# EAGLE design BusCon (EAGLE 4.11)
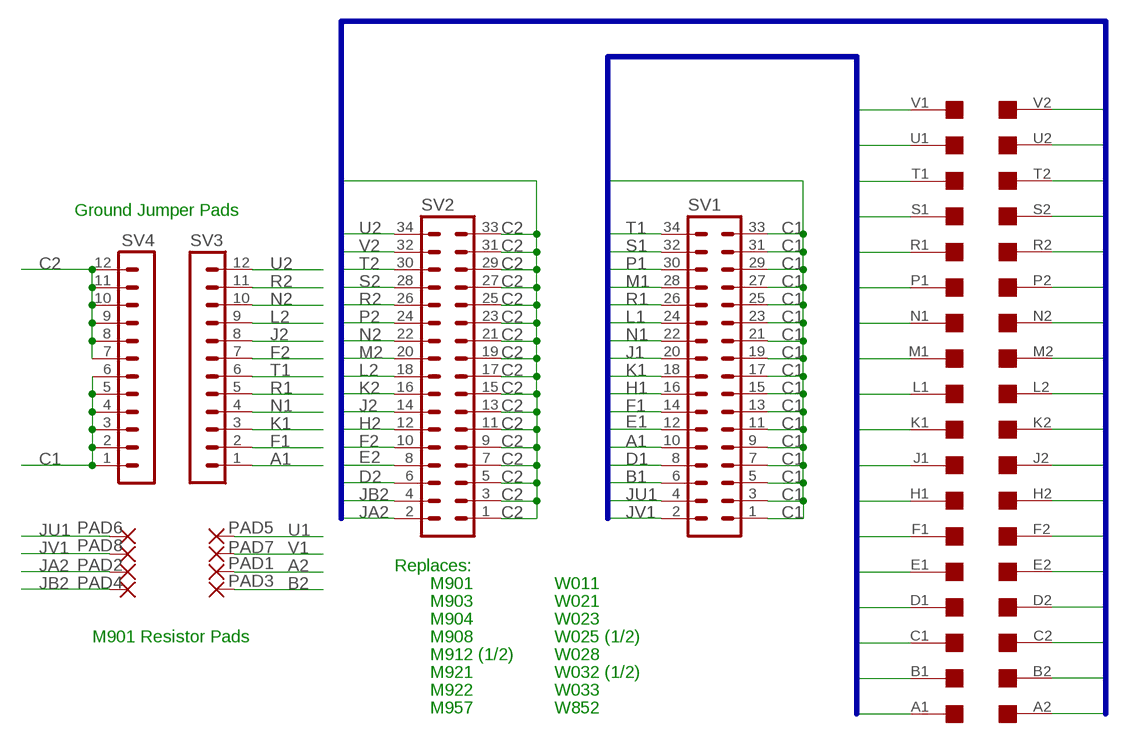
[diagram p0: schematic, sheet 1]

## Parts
PAD1  1,6/0,8  [1,6/0,8]
PAD2  1,6/0,8  [1,6/0,8]
PAD3  1,6/0,8  [1,6/0,8]
PAD4  1,6/0,8  [1,6/0,8]
PAD5  1,6/0,8  [1,6/0,8]
PAD6  1,6/0,8  [1,6/0,8]
PAD7  1,6/0,8  [1,6/0,8]
PAD8  1,6/0,8  [1,6/0,8]
SV1  MA17-2  [MA17-2]
SV2  MA17-2  [MA17-2]
SV3  MA12-1  [MA12-1]
SV4  MA12-1  [MA12-1]
U$4  EDGE-2  [EDGE-CON2]

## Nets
A1: SV1.10 SV3.1 U$4.A1
A2: PAD1.1(P) U$4.A2
B1: SV1.6 U$4.B1
B2: PAD3.1(P) U$4.B2
C1: SV1.1 SV1.3 SV1.5 SV1.7 SV1.9 SV1.11 SV1.13 SV1.15 SV1.17 SV1.19 SV1.21 SV1.23 SV1.25 SV1.27 SV1.29 SV1.31 SV1.33 SV4.1 SV4.2 SV4.3 SV4.4 SV4.5 SV4.6 U$4.C1
C2: SV2.1 SV2.3 SV2.5 SV2.7 SV2.9 SV2.11 SV2.13 SV2.15 SV2.17 SV2.19 SV2.21 SV2.23 SV2.25 SV2.27 SV2.29 SV2.31 SV2.33 SV4.7 SV4.8 SV4.9 SV4.10 SV4.11 SV4.12 U$4.C2
D1: SV1.8 U$4.D1
D2: SV2.6 U$4.D2
E1: SV1.12 U$4.E1
E2: SV2.8 U$4.E2
F1: SV1.14 SV3.2 U$4.F1
F2: SV2.10 SV3.7 U$4.F2
H1: SV1.16 U$4.H1
H2: SV2.12 U$4.H2
J1: SV1.20 U$4.J1
J2: SV2.14 SV3.8 U$4.J2
JA2: PAD2.1(P) SV2.2
JB2: PAD4.1(P) SV2.4
JU1: PAD6.1(P) SV1.4
JV1: PAD8.1(P) SV1.2
K1: SV1.18 SV3.3 U$4.K1
K2: SV2.16 U$4.K2
L1: SV1.24 U$4.L1
L2: SV2.18 SV3.9 U$4.L2
M1: SV1.28 U$4.M1
M2: SV2.20 U$4.M2
N1: SV1.22 SV3.4 U$4.N1
N2: SV2.22 SV3.10 U$4.N2
P1: SV1.30 U$4.P1
P2: SV2.24 U$4.P2
R1: SV1.26 SV3.5 U$4.R1
R2: SV2.26 SV3.11 U$4.R2
S1: SV1.32 U$4.S1
S2: SV2.28 U$4.S2
T1: SV1.34 SV3.6 U$4.T1
T2: SV2.30 U$4.T2
U1: PAD5.1(P) U$4.U1
U2: SV2.34 SV3.12 U$4.U2
V1: PAD7.1(P) U$4.V1
V2: SV2.32 U$4.V2

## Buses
A1,B1,C1,D1,E1,F1,H1,J1,K1,L1,M1,N1,P1,R1,S1,T1,U1,V1
A2,B2,C2,D2,E2,F2,H2,J2,K2,L2,M2,N2,P2,R2,S2,T2,U2,V2

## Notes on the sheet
- Ground Jumper Pads
- Replaces:
- M901 | W011
- M903 | W021
- M904 | W023
- M901 Resistor Pads | M908 | W025 (1/2)
- M912 (1/2) | W028
- M921 | W032 (1/2)
- M922 | W033
- M957 | W852

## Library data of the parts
PAD1-PAD8 = wirepad:1,6/0,8: THROUGH-HOLE PAD
SV1 SV2 = con-lstb:MA17-2: PIN HEADER
SV3 SV4 = con-lstb:MA12-1: PIN HEADER
U$4 = dec-con:EDGE-2: Double-Sided DEC edge connector.

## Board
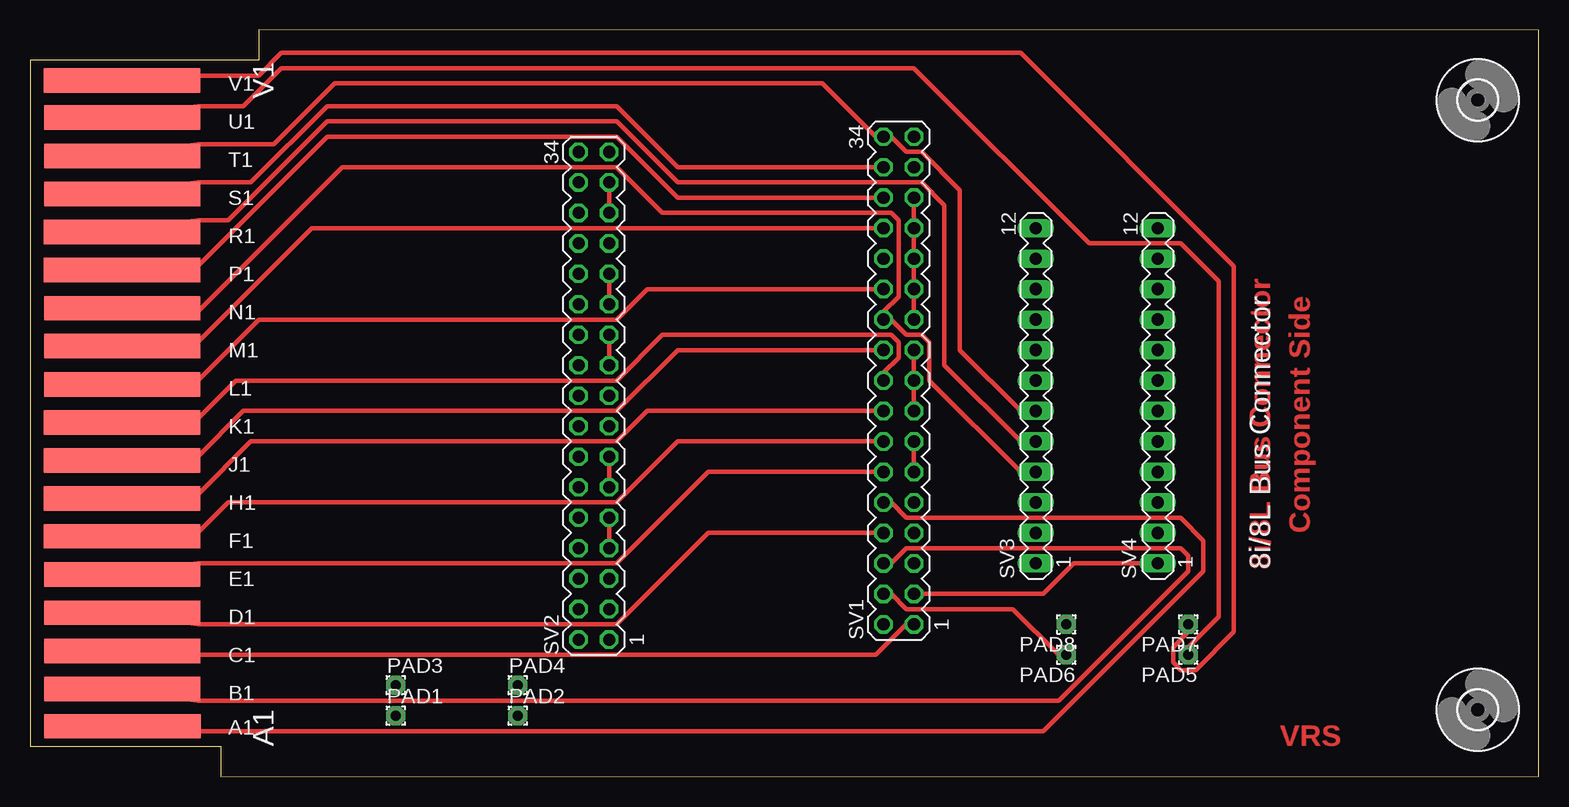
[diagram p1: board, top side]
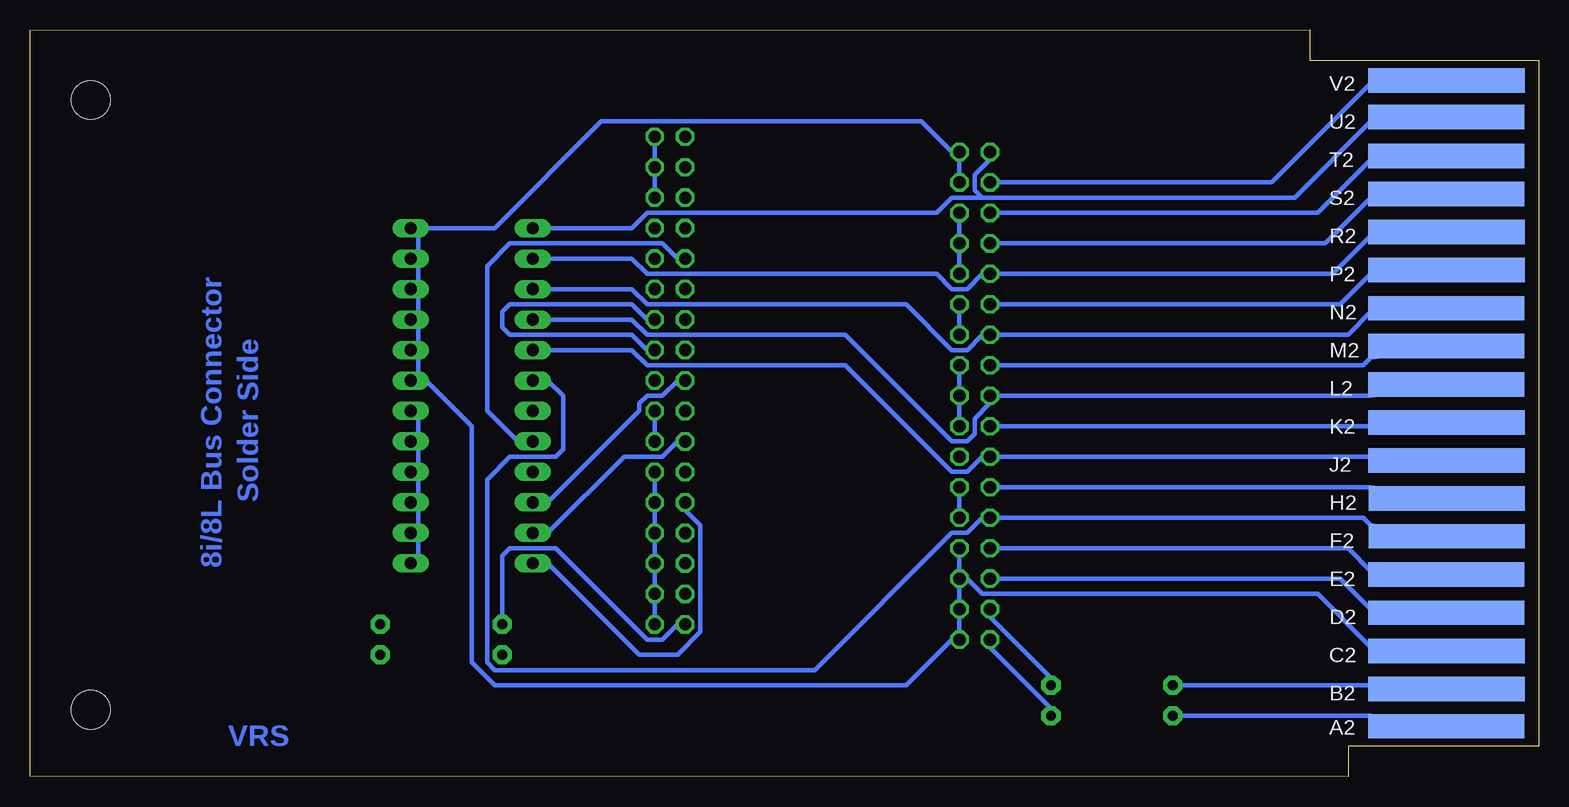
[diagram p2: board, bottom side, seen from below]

Size 125.72 x 62.23 mm. Coordinates in mm from the lower left corner, seen from the top.
Outline: 15.88,0 125.72,0.04 125.72,62.19 19.05,62.23
Copper layers (1*16): Top 0.035mm / dielectric 1.5mm / Bottom 0.035mm
Design rules "olimex10mil": minimum track width 15mil, minimum drill 24mil, track to track 15mil, track to pad 10mil, pad to pad 10mil, via to via 10mil, smd to smd 10mil, copper to edge 25mil, drill to drill 10mil, minimum pad ring 10mil, minimum via ring 8mil, stop-mask expansion 0mil, vias tented up to drill 0mil, thermal gap 10mil

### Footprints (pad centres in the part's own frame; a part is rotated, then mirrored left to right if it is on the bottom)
1,6/0,8 = drill 0.813 pad 1.6 octagon: 1 0,0
MA17-2 = drill 1.016 octagon: 1 -20.32,-1.27; 2 -20.32,1.27; 3 -17.78,-1.27; 4 -17.78,1.27; 5 -15.24,-1.27; 6 -15.24,1.27; 7 -12.7,-1.27; 8 -12.7,1.27; 9 -10.16,-1.27; 10 -10.16,1.27; 11 -7.62,-1.27; 12 -7.62,1.27; 13 -5.08,-1.27; 14 -5.08,1.27; 15 -2.54,-1.27; 16 -2.54,1.27; 17 0,-1.27; 18 0,1.27; 19 2.54,-1.27; 20 2.54,1.27; 21 5.08,-1.27; 22 5.08,1.27; 23 7.62,-1.27; 24 7.62,1.27; 25 10.16,-1.27; 26 10.16,1.27; 27 12.7,-1.27; 28 12.7,1.27; 29 15.24,-1.27; 30 15.24,1.27; 31 17.78,-1.27; 32 17.78,1.27; 33 20.32,-1.27; 34 20.32,1.27
MA12-1 = drill 1.016 long: 1 -13.97,0; 2 -11.43,0; 3 -8.89,0; 4 -6.35,0; 5 -3.81,0; 6 -1.27,0; 7 1.27,0; 8 3.81,0; 9 6.35,0; 10 8.89,0; 11 11.43,0; 12 13.97,0
3,2 = hole 3.2: 0,0
EDGE-CON2 = smd 13.017 x 2.032: A1 7.709,4.207; B1 7.684,7.312; C1 7.684,10.474; D1 7.684,13.665; E1 7.693,16.84; F1 7.668,20.041; H1 7.668,23.19; J1 7.668,26.34; K1 7.668,29.515; L1 7.693,32.69; M1 7.693,35.89; N1 7.693,39.04; P1 7.668,42.24; R1 7.668,45.39; S1 7.693,48.565; T1 7.693,51.74; U1 7.693,54.94; V1 7.668,58.026 | smd 13.017 x 2.032 bottom: A2 7.69,4.207; B2 7.668,7.328; C2 7.668,10.49; D2 7.693,13.665; E2 7.693,16.84; F2 7.642,20.041; H2 7.642,23.19; J2 7.668,26.34; K2 7.668,29.515; L2 7.693,32.69; M2 7.693,35.89; N2 7.693,39.04; P2 7.668,42.24; R2 7.668,45.39; S2 7.693,48.565; T2 7.693,51.74; U2 7.693,54.966; V2 7.668,58.026

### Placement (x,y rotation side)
PAD1  30.48,5.08 0 top
PAD2  40.64,5.08 0 top
PAD3  30.48,7.62 0 top
PAD4  40.64,7.62 0 top
PAD5  96.52,10.16 180 top
PAD6  86.36,10.16 180 top
PAD7  96.52,12.7 180 top
PAD8  86.36,12.7 180 top
SV1  72.39,33.02 90 top
SV2  46.99,31.75 90 top
SV3  83.82,31.75 90 top
SV4  93.98,31.75 90 top
U$2  [3,2]  120.65,5.59 0 top
U$3  [3,2]  120.65,56.39 0 top
U$4  0,0 0 top

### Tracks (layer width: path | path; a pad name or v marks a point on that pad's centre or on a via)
A1
  Top 0.381: SV1.10 71.76,22.86 73.03,21.59 95.89,21.59 97.79,19.68 97.79,17.14 84.46,3.81 13.97,3.81 U$4.A1
  Bottom 0.381: SV1.10 71.12,22.23 69.85,20.95 69.85,12.06 71.76,10.16 74.93,10.16 82.55,17.78 SV3.1
A2
  Bottom 0.381: PAD1.1 29.85,5.08 13.97,5.08 U$4.A2
B1
  Top 0.381: SV1.6 71.76,17.78 73.03,19.05 95.89,19.05 96.52,18.41 96.52,17.14 85.73,6.35 13.97,6.35 U$4.B1
B2
  Bottom 0.381: PAD3.1 29.85,7.62 13.97,7.62 U$4.B2
C1
  Top 0.381: SV1.21 73.66,38.73 73.66,40.01 SV1.23 73.66,41.27 73.66,42.55 SV1.25 73.66,43.81 73.66,45.09 SV1.27 73.66,46.35 73.66,47.62 SV1.29 | SV1.15 73.66,31.11 73.66,32.38 SV1.17 73.66,33.66 73.66,34.92 SV1.19 | SV1.13 73.66,27.3 73.66,26.04 SV1.11 | SV4.1 92.71,17.78 87,17.78 84.46,15.24 74.3,15.24 SV1.3 | U$4.C1 13.97,10.16 70.49,10.16 73.03,12.7 SV1.1
  Bottom 0.381: SV1.29 73.66,48.9 73.66,50.16 SV1.31 73.66,51.44 73.66,52.7 SV1.33 | SV4.1 93.35,18.41 93.35,19.68 SV4.2 93.35,20.95 93.35,22.23 SV4.3 93.35,23.5 93.35,24.77 SV4.4 93.35,26.04 93.35,27.3 SV4.5 93.35,28.57 93.35,29.84 SV4.6 | SV1.13 73.66,28.57 73.66,29.84 SV1.15 | SV1.1 73.66,13.34 73.66,14.61 SV1.3 73.66,15.88 73.66,17.14 SV1.5 73.66,18.41 73.66,19.68 SV1.7 73.66,20.95 73.66,22.23 SV1.9 73.66,23.5 73.66,24.77 SV1.11 | SV1.21 74.3,38.1 75.57,39.37 85.73,39.37 86.36,38.73 86.36,37.47 85.73,36.83 75.57,36.83 74.3,35.56 SV1.19
C2
  Top 0.381: SV2.21 48.26,36.2 48.26,34.92 SV2.19 | SV2.31 48.26,48.9 48.26,47.62 SV2.29 | SV2.23 48.26,40.01 48.26,41.27 SV2.25 | SV2.13 48.26,26.04 48.26,24.77 SV2.11 | SV2.9 48.26,20.95 48.26,19.68 SV2.7
  Bottom 0.381: SV2.21 48.26,37.47 48.26,38.73 SV2.23 | SV2.15 48.26,29.84 48.26,31.11 SV2.17 48.26,32.38 48.26,33.66 SV2.19 | SV2.31 48.26,50.16 48.26,51.44 SV2.33 48.9,52.07 51.44,54.61 78.11,54.61 87,45.72 92.71,45.72 SV4.12 93.35,45.09 93.35,43.81 SV4.11 93.35,42.55 93.35,41.27 SV4.10 93.35,40.01 93.35,38.73 SV4.9 93.35,37.47 93.35,36.2 SV4.8 93.35,34.92 93.35,33.66 SV4.7 92.71,33.02 88.9,29.21 88.9,9.53 87,7.62 52.71,7.62 48.9,11.43 SV2.1 48.26,12.06 48.26,13.34 SV2.3 48.26,14.61 48.26,15.88 SV2.5 | SV2.25 48.26,42.55 48.26,43.81 SV2.27 48.26,45.09 48.26,46.35 SV2.29 | SV2.9 48.26,22.23 48.26,23.5 SV2.11 | SV2.7 48.26,18.41 48.26,17.14 SV2.5 | SV2.5 47.63,16.51 46.36,15.24 18.42,15.24 13.97,10.79 U$4.C2
D1
  Top 0.381: SV1.8 70.49,20.32 56.52,20.32 48.9,12.7 13.97,12.7 U$4.D1
D2
  Bottom 0.381: SV2.6 45.09,16.51 16.51,16.51 13.97,13.97 U$4.D2
E1
  Top 0.381: SV1.12 70.49,25.4 56.52,25.4 48.9,17.78 13.97,17.78 U$4.E1
E2
  Bottom 0.381: SV2.8 45.09,19.05 15.88,19.05 13.97,17.14 U$4.E2
F1
  Top 0.381: SV1.14 70.49,27.94 53.98,27.94 48.9,22.86 16.51,22.86 13.97,20.32 U$4.F1
  Bottom 0.381: SV1.14 71.76,27.94 73.03,26.67 76.2,26.67 82.55,20.32 SV3.2
F2
  Bottom 0.381: U$4.F2 13.97,20.95 14.61,21.59 45.09,21.59 SV2.10 46.36,21.59 47.63,20.32 48.9,20.32 60.33,8.89 87,8.89 87.63,9.53 87.63,24.77 85.73,26.67 81.92,26.67 81.28,27.3 81.28,31.75 82.55,33.02 SV3.7
H1
  Top 0.381: SV1.16 70.49,30.48 51.44,30.48 48.9,27.94 18.42,27.94 13.97,23.5 U$4.H1
H2
  Bottom 0.381: SV2.12 45.09,24.13 13.97,24.13 U$4.H2
J1
  Top 0.381: SV1.20 70.49,35.56 53.98,35.56 48.9,30.48 17.78,30.48 13.97,26.67 U$4.J1
J2
  Bottom 0.381: U$4.J2 13.97,26.67 45.09,26.67 SV2.14 46.36,26.67 47.63,25.4 48.9,25.4 57.79,34.29 74.3,34.29 75.57,35.56 82.55,35.56 SV3.8
JA2
  Bottom 0.381: SV2.2 45.72,10.79 40.64,5.71 PAD2.1
JB2
  Bottom 0.381: SV2.4 45.72,13.34 40.64,8.26 PAD4.1
JU1
  Top 0.381: SV1.4 71.76,15.24 73.03,13.97 81.92,13.97 85.73,10.16 PAD6.1
JV1
  Bottom 0.381: SV1.2 71.76,12.7 73.03,11.43 74.3,11.43 81.92,19.05 85.73,19.05 86.36,18.41 86.36,13.34 PAD8.1
K1
  Top 0.381: SV1.18 71.12,33.66 72.39,34.92 72.39,36.2 71.76,36.83 52.71,36.83 48.9,33.02 17.15,33.02 13.97,29.84 U$4.K1
  Bottom 0.381: SV3.3 82.55,22.86 74.93,30.48 74.93,31.11 74.3,31.75 73.03,31.75 71.76,33.02 SV1.18
K2
  Bottom 0.381: SV2.16 45.09,29.21 13.97,29.21 U$4.K2
L1
  Top 0.381: SV1.24 70.49,40.64 51.44,40.64 48.9,38.1 19.05,38.1 13.97,33.02 U$4.L1
L2
  Bottom 0.381: U$4.L2 13.97,31.75 45.09,31.75 SV2.18 45.72,31.11 46.99,29.84 46.99,28.57 47.63,27.94 48.9,27.94 57.79,36.83 74.3,36.83 75.57,38.1 82.55,38.1 SV3.9
M1
  Top 0.381: SV1.28 70.49,45.72 23.5,45.72 13.97,36.2 U$4.M1
M2
  Bottom 0.381: SV2.20 45.09,34.29 14.61,34.29 13.97,34.92 U$4.M2
N1
  Top 0.381: SV3.4 82.55,25.4 74.93,33.02 74.93,36.2 74.3,36.83 73.03,36.83 71.76,38.1 SV1.22 71.12,38.73 72.39,40.01 72.39,46.35 71.76,46.99 52.71,46.99 48.9,50.8 26.04,50.8 13.97,38.73 U$4.N1
N2
  Bottom 0.381: U$4.N2 13.97,38.73 15.88,36.83 45.09,36.83 SV2.22 46.36,36.83 47.63,35.56 48.9,35.56 52.71,39.37 74.3,39.37 75.57,40.64 82.55,40.64 SV3.10
P1
  Top 0.381: SV1.30 70.49,48.26 53.98,48.26 48.9,53.34 24.77,53.34 13.97,42.55 U$4.P1
P2
  Bottom 0.381: SV2.24 45.09,39.37 16.51,39.37 13.97,41.91 U$4.P2
R1
  Top 0.381: SV3.5 82.55,27.94 76.2,34.29 76.2,47.62 74.3,49.53 53.98,49.53 48.9,54.61 24.77,54.61 16.51,46.35 13.97,46.35 U$4.R1
  Bottom 0.381: SV1.26 71.76,43.18 73.03,44.45 85.73,44.45 87.63,42.55 87.63,30.48 85.09,27.94 SV3.5
R2
  Bottom 0.381: U$4.R2 13.97,45.09 17.15,41.91 45.09,41.91 SV2.26 46.36,41.91 47.63,40.64 48.9,40.64 50.17,41.91 74.3,41.91 75.57,43.18 82.55,43.18 SV3.11
S1
  Top 0.381: SV1.32 70.49,50.8 53.98,50.8 48.9,55.88 24.77,55.88 18.42,49.53 13.97,49.53 U$4.S1
S2
  Bottom 0.381: SV2.28 45.09,44.45 17.78,44.45 13.97,48.26 U$4.S2
T1
  Top 0.381: SV3.6 82.55,30.48 77.47,35.56 77.47,48.9 74.3,52.07 73.03,52.07 71.76,53.34 SV1.34 70.49,53.34 66.04,57.78 25.4,57.78 20.32,52.7 13.97,52.7 U$4.T1
T2
  Bottom 0.381: SV2.30 45.09,46.99 18.42,46.99 13.97,51.44 U$4.T2
U1
  Top 0.381: PAD5.1 96.52,10.79 99.06,13.34 99.06,41.27 95.89,44.45 88.27,44.45 73.66,59.05 20.96,59.05 17.78,55.88 13.97,55.88 U$4.U1
U2
  Bottom 0.381: 46.36,48.26 46.99,48.9 46.99,50.16 45.72,51.44 SV2.34 | 46.36,48.26 20.32,48.26 13.97,54.61 U$4.U2 | 46.36,48.26 48.9,48.26 50.17,46.99 74.3,46.99 75.57,45.72 82.55,45.72 SV3.12
V1
  Top 0.381: PAD7.1 96.52,12.06 95.25,10.79 95.25,9.53 95.89,8.89 97.16,8.89 100.33,12.06 100.33,42.55 82.55,60.33 20.96,60.33 19.05,58.42 13.97,58.42 U$4.V1
V2
  Bottom 0.381: SV2.32 45.09,49.53 22.23,49.53 13.97,57.78 U$4.V2

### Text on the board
Top: Component Side | 8i/8L Bus Connector | VRS
Bottom: Solder Side | 8i/8L Bus Connector | VRS
tPlace: 8i/8L Bus Connector
tNames: V1 | A1
tValues: * | * | * | * | * | * | * | * | * | * | * | * | * | * | * | * | Jumper unless M901 | * | * | M90x/W0x1 - always used | M901/M903/M904 - Use both | M901 | 10ohm | M901 | * - Posibus/Negibus Signal | 10ohm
